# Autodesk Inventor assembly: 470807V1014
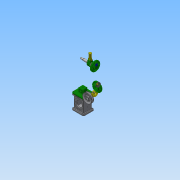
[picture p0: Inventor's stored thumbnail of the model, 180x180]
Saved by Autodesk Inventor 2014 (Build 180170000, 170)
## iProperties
Created: 2017-08
Part Number: 470807V1014
Document SubType Name: Assembly
Designer: 학생용
Author: 학생용
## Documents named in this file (18)
- C:\Users\학생용\Desktop\470807V1014\470807V1014.iam
- C:\Users\학생용\Desktop\470807V1014\470807V1014.ipt
- C:\Users\학생용\Desktop\470807V1014\E-링.ipt
- C:\Users\학생용\Desktop\470807V1014\V-벨트풀리.ipt
- C:\Users\학생용\Desktop\470807V1014\덮개.ipt
- C:\Users\학생용\Desktop\470807V1014\뒤커버.ipt
- C:\Users\학생용\Desktop\470807V1014\링크.ipt
- C:\Users\학생용\Desktop\470807V1014\베어링 17 x 40 x 12.ipt
- C:\Users\학생용\Desktop\470807V1014\볼트 M4 x 8.ipt
- C:\Users\학생용\Desktop\470807V1014\볼트 M4 x 10.ipt
- C:\Users\학생용\Desktop\470807V1014\슬라이더.ipt
- C:\Users\학생용\Desktop\470807V1014\앞커버.ipt
- C:\Users\학생용\Desktop\470807V1014\오일 실 17 30 8.ipt
- C:\Users\학생용\Desktop\470807V1014\와셔 4x16.ipt
- C:\Users\학생용\Desktop\470807V1014\클레비스 핀 6 x 22.ipt
- 클레비스 핀 6 x 22.ipt
- C:\Users\학생용\Desktop\470807V1014\키 4 x 4 x 12.ipt
- C:\Users\학생용\Desktop\470807V1014\편심축.ipt
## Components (3 placed, 3 different names)
1. 470807V1014:1
2. E-링:1
3. V-벨트풀리:1
